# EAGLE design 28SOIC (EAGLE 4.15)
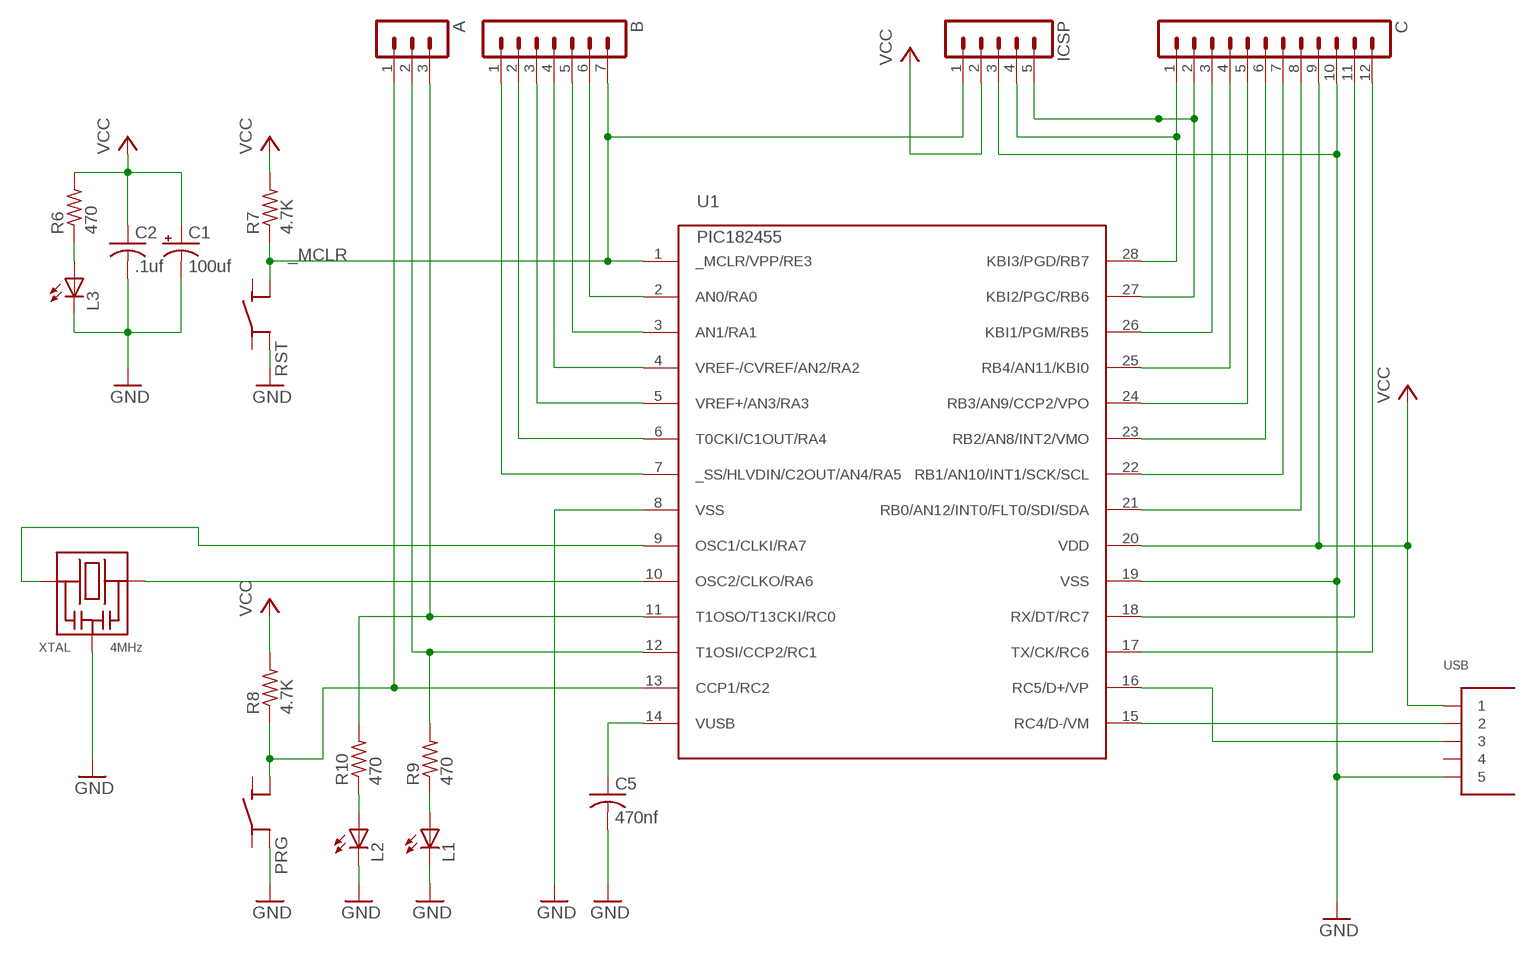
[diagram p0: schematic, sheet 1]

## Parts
A  MA03-1  [MA03-1]
B  MA07-1  [MA07-1]
C  MA12-1  [MA12-1]
C1  100uf  CAP_ELECTROLYTICSMT  [153CLV-0807]
C2  .1uf  C-USC1206  [C1206]
C5  470nf  C-USC1206  [C1206]
ICSP  MA05-1  [MA05-1]
L1  LEDCHIPLED_1206  [CHIPLED_1206]
L2  LEDCHIPLED_1206  [CHIPLED_1206]
L3  LEDCHIPLED_1206  [CHIPLED_1206]
PRG  SWITCH_DUAL  [SMT_SWITCH]
R6  470  R-US_M1206  [M1206]
R7  4.7K  R-US_M1206  [M1206]
R8  4.7K  R-US_M1206  [M1206]
R9  470  R-US_M1206  [M1206]
R10  470  R-US_M1206  [M1206]
RST  SWITCH_DUAL  [SMT_SWITCH]
U1  PIC182455  PIC182455-E/SO  [SO-28W]
USB  SMD_USB  [SMT_USB]
XTAL  4MHz  RESONATOR  [SMT_RESONATOR_3731]

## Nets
_MCLR: B.7 ICSP.1 R7.1 RST.P$4(P1) U1.1(_MCLR/VPP/RE3)
GND: C1.P$1(-) C2.2 C5.2 C.10 ICSP.3 L1.C L2.C L3.C PRG.P$2(P2) RST.P$2(P2) U1.8(VSS) U1.19(VSS) USB.P$5 XTAL.P$2(GND)
N$1: U1.16(RC5/D+/VP) USB.P$3
N$2: U1.15(RC4/D-/VM) USB.P$2
N$4: C.2 ICSP.5 U1.27(KBI2/PGC/RB6)
N$5: C5.1 U1.14(VUSB)
N$6: L2.A R10.1
N$7: A.1 PRG.P$4(P1) R8.1 U1.13(CCP1/RC2)
N$8: L1.A R9.1
N$9: L3.A R6.1
N$10: A.3 R10.2 U1.11(T1OSO/T13CKI/RC0)
N$11: A.2 R9.2 U1.12(T1OSI/CCP2/RC1)
N$12: C.1 ICSP.4 U1.28(KBI3/PGD/RB7)
N$14: C.3 U1.26(KBI1/PGM/RB5)
N$15: C.4 U1.25(RB4/AN11/KBI0)
N$16: C.5 U1.24(RB3/AN9/CCP2/VPO)
N$17: C.6 U1.23(RB2/AN8/INT2/VMO)
N$18: C.7 U1.22(RB1/AN10/INT1/SCK/SCL)
N$19: C.8 U1.21(RB0/AN12/INT0/FLT0/SDI/SDA)
N$20: B.6 U1.2(AN0/RA0)
N$21: B.5 U1.3(AN1/RA1)
N$22: B.4 U1.4(VREF-/CVREF/AN2/RA2)
N$23: B.3 U1.5(VREF+/AN3/RA3)
N$24: B.2 U1.6(T0CKI/C1OUT/RA4)
N$25: B.1 U1.7(_SS/HLVDIN/C2OUT/AN4/RA5)
N$26: C.12 U1.17(TX/CK/RC6)
N$27: C.11 U1.18(RX/DT/RC7)
N$28: U1.10(OSC2/CLKO/RA6) XTAL.P$3
N$31: U1.9(OSC1/CLKI/RA7) XTAL.P$1
VCC: C1.P$2(+) C2.1 C.9 ICSP.2 R6.2 R7.2 R8.2 U1.20(VDD) USB.P$1
Unconnected: PRG.P$1(P1) PRG.P$3(P2) RST.P$1(P1) RST.P$3(P2) USB.P$4

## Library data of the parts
A = UBW:MA03-1: PIN HEADER
B = UBW:MA07-1: PIN HEADER
C = UBW:MA12-1: PIN HEADER
C1 = UBW:CAP_ELECTROLYTIC
C2 C5 = rcl:C-US: CAPACITOR, American symbol
ICSP = UBW:MA05-1: PIN HEADER
L1-L3 = led:LED: LED
PRG RST = UBW:SWITCH_DUAL
R6-R10 = rcl:R-US_: RESISTOR, American symbol
U1 = UBW:PIC18*2455
USB = UBW:SMD_USB
XTAL = UBW:RESONATOR

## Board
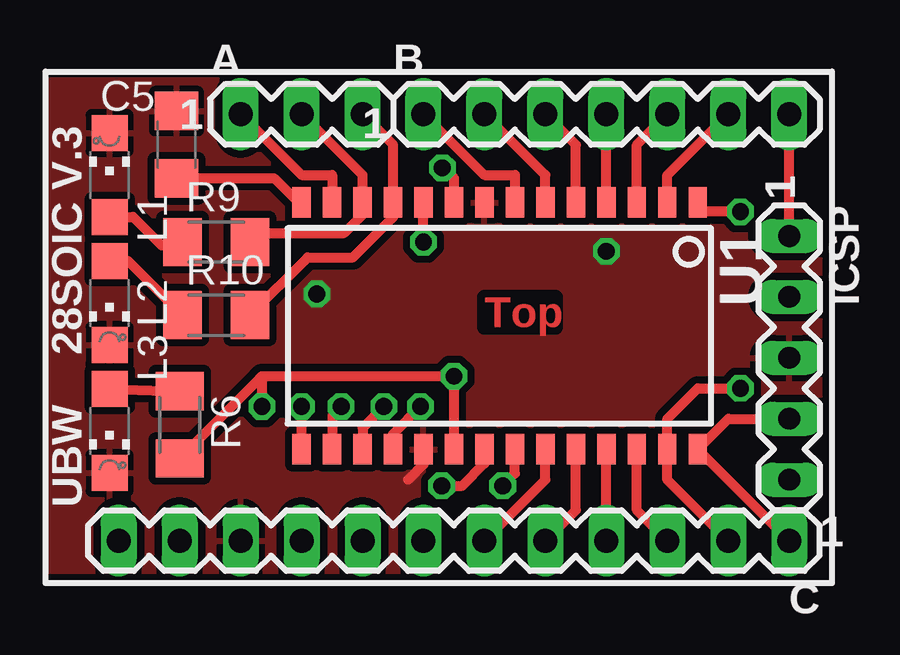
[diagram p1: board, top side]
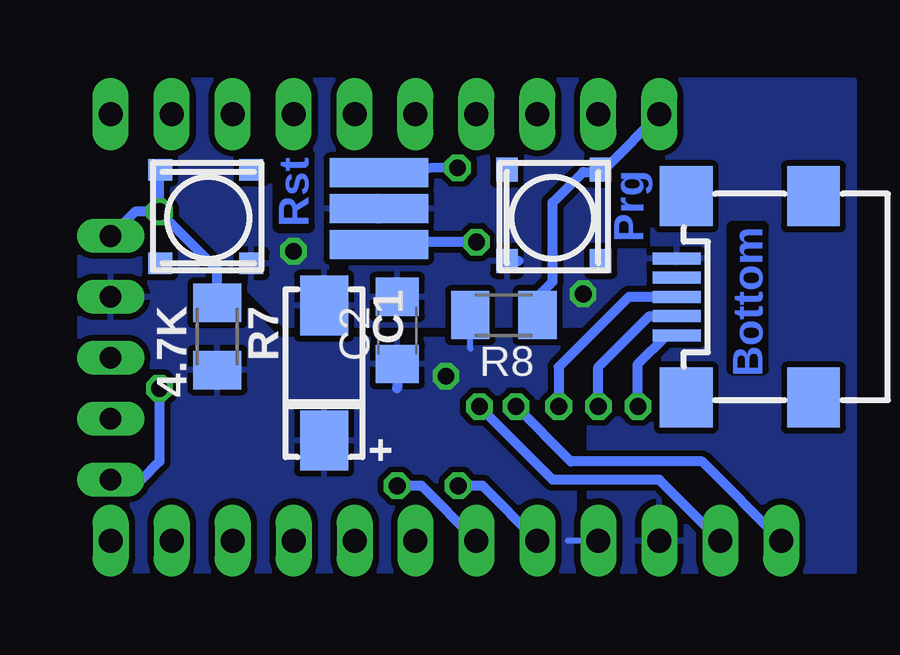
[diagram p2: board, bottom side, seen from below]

No outline drawn. Coordinates in mm, seen from the top.
Copper layers (1*16): Top 0.035mm / dielectric 1.5mm / Bottom 0.035mm
Design rules "New Text Document": minimum track width 10mil, minimum drill 24mil, track to track 10mil, track to pad 10mil, pad to pad 10mil, via to via 10mil, smd to smd 10mil, copper to edge 40mil, drill to drill 10mil, minimum pad ring 10mil, minimum via ring 8mil, stop-mask expansion 0mil, vias tented up to drill 0mil, thermal gap 10mil

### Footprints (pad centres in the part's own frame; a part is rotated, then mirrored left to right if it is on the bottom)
MA03-1 = drill 1 long: 1 -2.54,0; 2 0,0; 3 2.54,0
MA07-1 = drill 1 long: 1 -7.62,0; 2 -5.08,0; 3 -2.54,0; 4 0,0; 5 2.54,0; 6 5.08,0; 7 7.62,0
MA12-1 = drill 1 long: 1 -13.97,0; 2 -11.43,0; 3 -8.89,0; 4 -6.35,0; 5 -3.81,0; 6 -1.27,0; 7 1.27,0; 8 3.81,0; 9 6.35,0; 10 8.89,0; 11 11.43,0; 12 13.97,0
153CLV-0807 = smd 2.5 x 2: P$1 -2.81,0; P$2 2.81,0
C1206 = smd 1.6 x 1.8: 1 -1.4,0; 2 1.4,0
MA05-1 = drill 0.9 long: 1 -5.08,0; 2 -2.54,0; 3 0,0; 4 2.54,0; 5 5.08,0
CHIPLED_1206 = smd 1.5 x 1.5: A 0,-1.75; C 0,1.75
SMT_SWITCH = smd 0.9 x 1: P$1 -2,1.8; P$2 1.9,1.8; P$3 1.9,-2; P$4 -2,-2
M1206 = smd 1.6 x 2: 1 -1.4,0; 2 1.4,0
SO-28W = smd 0.762 x 1.27: 1 -7.62,-5.207; 2 -6.35,-5.207; 3 -5.08,-5.207; 4 -3.81,-5.207; 5 -2.54,-5.207; 6 -1.27,-5.207; 7 0,-5.207; 8 1.27,-5.207; 9 2.54,-5.207; 10 3.81,-5.207; 11 5.08,-5.207; 12 6.35,-5.207; 13 7.62,-5.207; 14 8.89,-5.207; 15 8.89,5.08; 16 7.62,5.08; 17 6.35,5.08; 18 5.08,5.08; 19 3.81,5.08; 20 2.54,5.08; 21 1.27,5.08; 22 0,5.08; 23 -1.27,5.08; 24 -2.54,5.08; 25 -3.81,5.08; 26 -5.08,5.08; 27 -6.35,5.08; 28 -7.62,5.08
SMT_USB = smd 0.5 x 2: P$1 -1.6,8.8; P$2 -0.8,8.8; P$3 0,8.8; P$4 0.8,8.8; P$5 1.6,8.8 | smd 2.5 x 2.2: P$6 -4.2,8.4; P$7 4.2,8.4; P$8 4.2,3.1; P$9 -4.2,3.1
SMT_RESONATOR_3731 = smd 1.2 x 4.1: P$1 -1.5,0; P$2 0,0; P$3 1.5,0

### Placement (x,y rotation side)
A  11.43,19.05 0 top
B  24.13,19.05 0 top
C  17.78,1.27 180 top
C1  22.86,8.26 270 bottom
C2  19.81,10.03 90 bottom
C5  6.22,17.78 90 top
ICSP  31.75,8.89 270 top
L1  3.43,16.51 0 top
L2  3.43,11.18 180 top
L3  3.43,5.84 180 top
PRG  13.34,14.73 180 bottom
R6  6.35,6.1 270 top
R7  27.3,9.78 270 bottom
R8  15.37,10.67 180 bottom
R9  7.87,13.72 0 top
R10  7.87,10.67 0 top
RST  27.69,14.73 270 bottom
U1  20.32,10.16 180 top
USB  -0.64,11.43 90 bottom
XTAL  20.57,15.11 270 bottom

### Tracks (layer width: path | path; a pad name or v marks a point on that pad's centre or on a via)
_MCLR  (via drill 0.7)
  Top 0.406: ICSP.1 B.7 | v29.72,14.99 27.94,14.99 U1.1 27.94,15.24
  Bottom 0.406: v29.72,14.99 29.72,16.76 RST.P$4 | v29.72,14.99 30.73,14.99 ICSP.1 | R7.1 27.3,12.57 v29.72,14.99
GND  (via drill 0.7, 0.7 pad 1.02)
  Top 0.406: U1.19 16.51,4.45 15.88,3.81
  Bottom 0.406: C.10 8.89,2.54 | PRG.P$2 14.75,12.93 | C2.2 | USB.P$5 7.58,13.08 8.89,13.08
  other vias: 12.06,11.56 24.13,13.34
  pour Top (isolate 0.305): 0.76,20.45 0.76,0 33.02,0 33.02,20.45
  pour Bottom: 0.76,20.45 33.02,20.45 33.02,14.22 28.45,14.22 24.51,10.29 11.81,10.29 11.81,0 0.76,0
N$1  (via drill 0.7)
  Top 0.406: v13.08,6.86 12.71,6.48 12.7,5.59 | 12.7,5.59 12.7,5.6 | 12.7,5.59 U1.16
  Bottom 0.406: v13.08,6.86 13.08,8.51 10.16,11.43 USB.P$3
N$2  (via drill 0.7)
  Top 0.406: 11.43,6.99 v11.43,6.86 U1.15
  Bottom 0.406: v11.43,6.86 11.43,8.51 9.31,10.63 USB.P$2
N$4  (via drill 0.7)
  Top 0.406: U1.27 26.67,4.66 | U1.27 26.67,6.35 27.94,7.62 v29.72,7.62 | C.2 26.67,3.81 U1.27
  Bottom 0.406: v29.72,7.62 29.72,4.57 30.48,3.81 ICSP.5
N$5
  Top 0.406: C5.1 10.29,16.38 11.43,15.24 U1.14
N$6
  Top 0.406: R10.1 5.84,11.3 4.22,12.93 L2.A
N$7
  Top 0.406: A.1 11.43,16.51 12.7,16.51 U1.13
  Bottom 0.406: A.1 11.05,16.89 PRG.P$4 11.3,16.64 12.06,16.64 13.34,15.37 13.34,12.06 13.97,11.43 R8.1
N$8
  Top 0.406: L1.A 4.42,14.76 5.59,13.59 R9.1
N$9
  Top 0.406: L3.A R6.1
N$10
  Top 0.406: R10.2 11.68,13.08 13.57,13.08 15.24,14.75 U1.11 15.24,17.78 A.3
N$11
  Top 0.406: R9.2 9.4,14.1 13.21,14.1 13.97,14.86 U1.12 13.97,16.51 A.2
N$12
  Top 0.406: C.1 U1.28 29.21,6.35 ICSP.4
N$14
  Top 0.406: U1.26 25.4,2.54 C.3
N$15
  Top 0.406: C.4 U1.25
N$16
  Top 0.406: U1.24 22.86,2.54 C.5
N$17
  Top 0.406: U1.23 21.59,3.81 C.6
N$18  (via drill 0.7)
  Top 0.406: v19.81,3.56 20.32,4.06 U1.22
  Bottom 0.406: C.7 18.8,3.56 v19.81,3.56
N$19  (via drill 0.7)
  Top 0.406: v17.27,3.56 18.12,3.56 19.05,4.48 U1.21
  Bottom 0.406: v17.27,3.56 16.26,3.56 C.8
N$20
  Top 0.406: U1.2 26.67,16.51 B.6
N$21
  Top 0.406: U1.3 25.4,17.78 B.5
N$22
  Top 0.406: U1.4 B.4
N$23
  Top 0.406: U1.5 22.86,17.78 B.3
N$24
  Top 0.406: B.2 21.59,16.51 U1.6
N$25
  Top 0.406: U1.7 20.32,16.51 19.05,16.51 B.1
N$26  (via drill 0.7)
  Top 0.406: v14.86,6.86 13.97,5.97 U1.17
  Bottom 0.406: C.12 7.11,4.57 12.57,4.57 v14.86,6.86
N$27  (via drill 0.7)
  Top 0.406: v16.38,6.86 15.24,5.71 U1.18
  Bottom 0.406: v16.38,6.86 13.34,3.81 8.89,3.81 C.11
N$28  (via drill 0.7)
  Top 0.406: v16.51,13.72 U1.10
  Bottom 0.406: XTAL.P$3 20.83,13.72 v16.51,13.72
N$31  (via drill 0.7 pad 1.02)
  Top 0.406: U1.9 17.78,16.38 v17.3,16.82
  Bottom 0.406: v17.3,16.82 20.7,16.76 XTAL.P$1
VCC  (via drill 0.7)
  Top 0.406: 17.78,7.63 U1.20 | 17.78,7.63 v17.78,8.13 | 17.78,7.63 17.79,8.13 9.78,8.13 | 9.78,8.13 v9.78,6.86 | R6.2 9.53,7.87 9.78,8.13
  Bottom 0.254: R8.2 16.77,9.27 16.76,9.27 | C.9 12.7,1.27
  Bottom 0.406: C2.1 19.81,7.62 | R7.2 | R8.2 17.27,10.67 | v9.78,6.86 9.78,8.64 8.59,9.83 USB.P$1
  pour Bottom: 12.45,9.65 12.45,0 33.02,0 33.02,13.72 28.83,13.72 24.77,9.65

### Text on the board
Top: Top
Bottom: Bottom | Prg | Rst
tPlace: 28SOIC V.3 | UBW
tNames: 1 | 1 | 1 | 1
bNames: R7 | 4.7K | +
